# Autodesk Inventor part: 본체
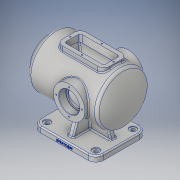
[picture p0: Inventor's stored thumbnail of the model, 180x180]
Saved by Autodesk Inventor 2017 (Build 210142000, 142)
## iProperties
Part Number: 본체
Material: 알루미늄 6061
Document SubType Name: Modeling
Designer: Administrator
Density: 2.7 g/cm^3
Appearance: 알루미늄 - 평지
Mass: 3571.01 g
Surface Area: 2403.85 cm^2
Volume: 1322.6 cm^3
Author: Administrator
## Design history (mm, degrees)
sketch "스케치1"
  geometry: L1 (80, 65)-(-80, 65); L2 (-80, 65)-(-80, -65); L3 (-80, -65)-(80, -65); L4 (80, -65)-(80, 65); L5 (80, 65)-(-80, -65); L6 (-80, 65)-(80, -65); 1 further point
  constraints: 12 end point, 2 midpoint, 2 parallel, 1 horizontal, 1 perpendicular
  dimensions: "d0" = 160 distance of L3.end L2.end; "d1" = 130 distance of L2.end L1.end
extrude "돌출1" new body sketch "스케치1" distance "d2" = 14; taper "d3" = 0 deg
sketch "스케치2"
  geometry: L1 (80, 0)-(-80, 0) reference; L2 (-80, 0)-(-80, 14) reference; L3 (-95, 179)-(-95, 161.5); L4 (-95, 161.5)-(-105, 161.5); L5 (-105, 161.5)-(-105, 114); L6 (-105, 114)-(105, 114); L7 (-95, 179)-(80.993, 179); L8 (-80, 0)-(80, 0) reference; A1 r 100 centre (5, 114) between (105, 114) and (80.993, 179); 3 further points
  constraints: 10 end point, 2 horizontal, 2 midpoint, 2 perpendicular, 2 point on circle, 1 centre point, 1 point on line, 1 vertical alignment
  dimensions: "d89" = 10 distance of L3.end L4.end; "d101" = 210 distance of L6.end L5.end; "d103" = 114 distance between parallel lines of L6 L1; "d105" = 95 diameter of L4 L6; "d106" = 200 diameter of A1; "d108" = 130 diameter of L7 L6
revolve "회전2" sketch "스케치2" stored, may be unused: angle "d19" = 90 deg
sketch "스케치3"
  geometry: L1 (80, 65)-(-80, 65) reference; L2 (-80, 65)-(-80, -65) reference; L3 (80, -65)-(80, 65) reference; L4 (-80, -65)-(80, -65) reference; 5 further points
  constraints: 2 horizontal alignment, 2 vertical alignment
  dimensions: "d22" = 18 distance from line of point (-62, 47) L1; "d23" = 18 distance from line of point (-62, 47) L2; "d24" = 18 distance from line of point (62, 47) L3; "d25" = 18 distance from line of point (62, -47) L4
hole "구멍1" sketch "스케치3" at (-62, 47), (62, 47), (62, -47), (-62, -47) diameter "d26" = 18; stored, may be unused: countersink angle "d30" = 90 deg, drill point angle "d32" = 0 deg; dims "d27" = 6, "d28" = 4, "d29" = 2, "d31" = 2
sketch "스케치4"
  geometry: C1 r 9 at (-62, 47) reference; C2 r 9 at (-62, -47) reference; C3 r 9 at (62, -47) reference; C4 r 9 at (62, 47) reference; 5 further points
  constraints: 4 coincident
hole "구멍2" sketch "스케치4" at (-62, 47), (-62, -47), (62, -47), (62, 47) diameter "d33" = 9; stored, may be unused: countersink angle "d37" = 90 deg, drill point angle "d39" = 118 deg; dims "d34" = 6, "d35" = 4, "d36" = 2, "d38" = 2
node "작업 평면1"
sketch "스케치11"
  geometry: L1 (-39.982, 69)-(39.982, 69); L2 (80, 0)-(-80, 0) reference; L3 (-39.982, 69)-(-60, 14); L4 (80, 14)-(-80, 14) reference; L5 (60, 14)-(39.982, 69); L6 (-60, 14)-(60, 14); 6 further points
  constraints: 8 end point, 3 midpoint, 3 point on line, 2 vertical alignment, 1 coincident, 1 collinear, 1 horizontal
  dimensions: "d227" = 110 deg angle of L5 L4; "d228" = 110 deg angle of L4 L3; "d229" = 55 distance between parallel lines of L1 L4; "d230" = 120 distance of L5.start L3.end
extrude "돌출6" join sketch "스케치11" stored distance "d114" = 14; taper "d115" = 0 deg
sketch "스케치12"
  geometry: L1 (0, -65)-(0, 65) reference; L2 (69, 29.982)-(69, -29.982); L3 (69, 29.982)-(14, 50); L4 (14, -65)-(14, 65) reference; L5 (14, -50)-(69, -29.982); L6 (14, 50)-(14, -50); 5 further points
  constraints: 8 end point, 3 point on line, 2 coincident, 2 midpoint, 2 vertical, 1 horizontal alignment
  dimensions: "d223" = 110 deg angle of L5 L4; "d224" = 110 deg angle of L4 L3; "d225" = 100 distance of L5.start L3.end; "d226" = 55 distance between parallel lines of L2 L4
extrude "돌출7" join sketch "스케치12" stored distance "d120" = 14; taper "d121" = 0 deg
node "작업 평면2"
sketch "스케치14"
  geometry: L1 (55, -30)-(-65, -30); L2 (-65, -30)-(-65, 30); L3 (-65, 30)-(55, 30); L4 (55, 30)-(55, -30); L5 (105, 47.5)-(105, -47.5) reference; 2 further points
  constraints: 8 end point, 2 parallel, 1 horizontal, 1 horizontal alignment, 1 midpoint, 1 perpendicular
  dimensions: "d132" = 120 distance of L1.start L1.end; "d133" = 60 distance of L3.end L1.start; "d145" = 50 distance between parallel lines of L4 L5
extrude "돌출8" join sketch "스케치14" stored distance "d135" = 14; taper "d136" = 0 deg
sketch "스케치15"
  geometry: L1 (40, -20)-(-50, -20); L2 (-55, -15)-(-55, 15); L3 (-50, 20)-(40, 20); L4 (45, 15)-(45, -15); L5 (55, -30)-(-65, -30) reference; L6 (-65, -30)-(-65, 30) reference; L7 (55, 30)-(55, -30) reference; A1 r 5 centre (40, -15) between (40, -20) and (45, -15); A2 r 5 centre (40, 15) between (45, 15) and (40, 20); A3 r 5 centre (-50, 15) between (-50, 20) and (-55, 15); A4 r 5 centre (-50, -15) between (-55, -15) and (-50, -20); 2 further points
  constraints: 8 end point, 8 point on circle, 8 tangent, 4 centre point, 3 equal radius, 2 parallel, 1 horizontal, 1 horizontal alignment, 1 midpoint, 1 perpendicular
  dimensions: "d137" = 10 distance between parallel lines of L1 L5; "d138" = 10 distance between parallel lines of L2 L6; "d139" = 10 distance between parallel lines of L7 L4; "d140" = 5 radius of A1 (derived)
extrude "돌출9" cut sketch "스케치15" distance "d141" = 50; taper "d142" = 0 deg
fillet "모깎기1" dims "d143" = 15
sketch "스케치17"
  geometry: L1 (-65, -15)-(-65, 15) reference; 5 further points
  constraints: 2 horizontal alignment, 1 vertical alignment
  dimensions: "d146" = 50 distance of point (-5, 25) point (-5, -25); "d147" = 55 horizontal distance of point (-5, -25) point (50, 0); "d148" = 55 horizontal distance of point (-60, 0) point (-5, -25); "d150" = 60 distance from line of point (-5, -25) L1; "d151" = 25 vertical distance of point (-5, -25) point (0, 0)
hole "구멍4" sketch "스케치17" at (-5, -25), (50, 0), (-5, 25), (-60, 0) diameter "d152" = 3.242; stored, may be unused: countersink angle "d156" = 90 deg, drill point angle "d158" = 118 deg; dims "d153" = 9, "d154" = 4, "d155" = 2, "d157" = 11
node "작업 평면3"
sketch "스케치19"
  geometry: L1 (-105, 66.5)-(-105, 161.5) reference; C1 r 40 at (22, 114); 1 further point
  constraints: 1 centre point
  dimensions: "d165" = 80 diameter of C1; "d166" = 114 vertical distance of C1.centre point (0, 0); "d167" = 127 distance from line of C1.centre L1
extrude "돌출11" join sketch "스케치19" distance "d168" = 150; taper "d169" = 0 deg
sketch "스케치20"
  geometry: C1 r 40 at (0, 0) reference; C2 r 26 at (0, 0); 1 further point
  constraints: 1 centre point, 1 coincident
  dimensions: "d170" = 52 diameter of C2
extrude "돌출12" cut sketch "스케치20" distance "d171" = 18; taper "d172" = 0 deg
sketch "스케치21"
  geometry: C1 r 40 at (0, 0) reference; C2 r 26 at (0, 0); 1 further point
  constraints: 1 centre point, 1 coincident
  dimensions: "d174" = 52 diameter of C2
extrude "돌출13" cut sketch "스케치21" distance "d175" = 18; taper "d176" = 0 deg
sketch "스케치22"
  geometry: C1 r 26 at (0, 0) reference; C2 r 21 at (0, 0); 1 further point
  constraints: 1 centre point, 1 coincident
  dimensions: "d178" = 42 diameter of C2
extrude "돌출14" cut sketch "스케치22" stored distance "d179" = 18; taper "d180" = 0 deg
sketch "스케치23"
  geometry: C1 r 21 at (0, 0) reference; A1 r 32.5 centre (0, 0) between (0, 32.5) and (-32.5, 0); 3 further points
  constraints: 4 point on circle, 2 horizontal alignment, 2 vertical alignment, 1 centre point, 1 coincident
  dimensions: "d182" = 65 diameter of A1
hole "구멍5" sketch "스케치23" at (0, 32.5), (-32.5, 0), (0, -32.5), (32.5, 0) diameter "d183" = 3.242; stored, may be unused: countersink angle "d187" = 90 deg, drill point angle "d189" = 118 deg; dims "d184" = 11, "d185" = 4, "d186" = 2, "d188" = 13
sketch "스케치24"
  geometry: L1 (-105, 66.5)-(-105, 161.5) reference; L2 (-105, 114)-(-105, 146.5); L3 (-105, 146.5)-(-80, 146.5); L4 (-80, 146.5)-(-80, 169); L5 (-80, 169)-(76.239, 169); L6 (95, 114)-(-105, 114); L7 (80, 0)-(-80, 0) reference; A1 r 90 centre (5, 114) between (95, 114) and (76.239, 169); 1 further point
  constraints: 10 end point, 2 perpendicular, 2 point on circle, 2 point on line, 1 centre point, 1 horizontal, 1 midpoint
  dimensions: "d191" = 114 distance between parallel lines of L6 L7; "d193" = 65 diameter of L3 L6; "d194" = 110 diameter of L5 L6; "d195" = 25 distance of L2.end L3.end; "d198" = 110 distance from line of A1.centre L1; "d199" = 90 radius of A1
revolve "회전5" sketch "스케치24" stored, may be unused: angle "d200" = 90 deg
sketch "스케치25"
  geometry: C1 r 32.5 at (0, 0) reference; A1 r 40 centre (0, 0) between (0, 40) and (-40, 0); 3 further points
  constraints: 4 point on circle, 2 horizontal alignment, 2 vertical alignment, 1 centre point, 1 coincident
  dimensions: "d201" = 80 diameter of A1
hole "구멍6" sketch "스케치25" at (0, 40), (-40, 0), (0, -40), (40, 0) diameter "d202" = 3.242; stored, may be unused: countersink angle "d206" = 90 deg, drill point angle "d208" = 118 deg; dims "d203" = 11, "d204" = 4, "d205" = 2, "d207" = 13
fillet "모깎기2" dims "d209" = 3, "d210" = 20
fillet "모깎기4" dims "d212" = 10
fillet "모깎기5" dims "d213" = 10
chamfer "모따기1" distance "d214" = 1; stored, may be unused: second distance "d215" = 2, angle "d216" = 45 deg
fillet "모깎기7" dims "d218" = 3
node "작업 평면4"
sketch "스케치26"
  geometry: 2 further points
  constraints: 1 vertical alignment, 1 other
  dimensions: "d220" = 5 distance of point (0, 5) point (0, 0)
feature "엠보싱1" sketch "스케치26" dims "d221" = 0.5, "d222" = 0
fillet "모깎기9" dims "d232" = 3
fillet "모깎기10" dims "d233" = 0.3
fillet "모깎기11" dims "d234" = 3
node "솔리드1"
mirror "미러1"
other parameters: "d54" = 184, "d131" = 184, "d164" = 75
